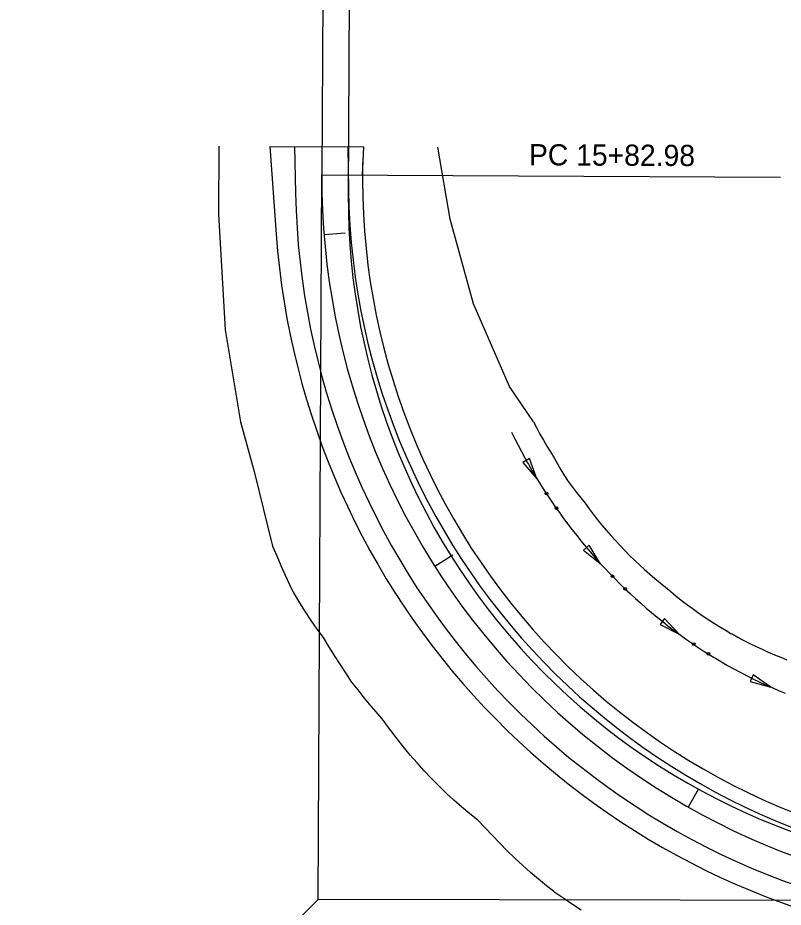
# Model space of a CAD drawing. Extents: x 1311167 to 1314552, y 2087587 to 2090602.
# Drawn here: x 1313606.1 to 1313823, y 2088407.4 to 2088659.3 of the extents above; entities that cross this region are included whole.
import ezdxf

# ---------------------------------------------------------------- set-up
doc = ezdxf.new("R2010")
doc.units = 0
for name, color, linetype in [('R_Horz Alg Stationing', 7, 'Continuous'), ('R_Proposed Road', 7, 'Continuous'), ('R_Shld_GR', 7, 'Continuous'), ('R_Shoulder', 7, 'Continuous'), ('S_DITCHLINE', 7, 'Continuous'), ('S_EDGE_CONCRETE', 7, 'Continuous'), ('S_EDGE_PAVEMENT', 7, 'Continuous'), ('S_PAVEMENT_CROWN', 7, 'Continuous')]:
    doc.layers.add(name, color=color, linetype=linetype)

msp = doc.modelspace()

# ---------------------------------------------------------------- linework, layer by layer
at = {"layer": 'R_Horz Alg Stationing'}
msp.add_line((1313700.19, 2088707.54), (1313699.7, 2088609.29), dxfattribs=at)
msp.add_arc((1313890.67, 2088608.34), 190.97, 179.7167, 269.7667, dxfattribs=at)
at = {"layer": 'R_Proposed Road'}
msp.add_line((1313692.64, 2088697.84), (1313692.23, 2088614.86), dxfattribs=at)
msp.add_line((1313692.64, 2088697.84), (1313692.23, 2088614.86), dxfattribs=at)
msp.add_arc((1313896.86, 2088613.85), 204.63, 179.7167, 269.8833, dxfattribs=at)
msp.add_arc((1313896.86, 2088613.85), 204.63, 179.7167, 269.8833, dxfattribs=at)
at = {"layer": 'R_Shld_GR'}
for points in [[(1313896.44, 2088409.22), (1313691.22, 2088409.64), (1313692.23, 2088614.86)], [(1313692.23, 2088614.86), (1313822.23, 2088614.22)], [(1313691.22, 2088409.64), (1313606.07, 2088325.08)]]:
    msp.add_lwpolyline(points, dxfattribs=at)
at = {"layer": 'R_Shoulder'}
for points in [[(1313698.84, 2088598.33), (1313692.86, 2088597.86)], [(1313729.3, 2088507.18), (1313724.24, 2088503.96)], [(1313799, 2088441), (1313796.04, 2088435.78)]]:
    msp.add_lwpolyline(points, dxfattribs=at)
at = {"layer": 'S_DITCHLINE'}
for p, q in [((1313751.04, 2088534.49), (1313749.22, 2088533.42)), ((1313749.22, 2088533.42), (1313753.15, 2088528.77)), ((1313753.15, 2088528.77), (1313751.04, 2088534.49)), ((1313767.98, 2088509.97), (1313766.38, 2088508.58)), ((1313771.13, 2088504.75), (1313767.98, 2088509.97)), ((1313766.38, 2088508.58), (1313771.13, 2088504.75)), ((1313789.32, 2088489.21), (1313788.05, 2088487.52)), ((1313788.05, 2088487.52), (1313793.47, 2088484.74)), ((1313793.47, 2088484.74), (1313789.32, 2088489.21)), ((1313814.45, 2088473.25), (1313813.55, 2088471.33)), ((1313819.44, 2088469.75), (1313814.45, 2088473.25)), ((1313813.55, 2088471.33), (1313819.44, 2088469.75))]:
    msp.add_line(p, q, dxfattribs=at)
for points in [[(1313745.99, 2088541.94), (1313746.89, 2088540.11), (1313747.82, 2088538.3), (1313748.77, 2088536.49), (1313749.74, 2088534.69), (1313750.53, 2088533.27), (1313750.74, 2088532.91), (1313751.77, 2088531.15), (1313752.81, 2088529.4), (1313753.88, 2088527.66), (1313754.98, 2088525.94), (1313756.09, 2088524.23), (1313757.22, 2088522.53), (1313758.37, 2088520.85), (1313759.55, 2088519.19), (1313760.74, 2088517.53), (1313761.95, 2088515.9), (1313763.18, 2088514.28), (1313764.44, 2088512.67), (1313765.71, 2088511.08), (1313767.01, 2088509.51), (1313768.33, 2088507.96), (1313769.66, 2088506.43), (1313771.02, 2088504.91), (1313772.4, 2088503.42), (1313773.8, 2088501.94), (1313775.22, 2088500.49), (1313776.65, 2088499.05), (1313778.11, 2088497.63), (1313779.58, 2088496.24), (1313781.08, 2088494.86), (1313782.59, 2088493.51), (1313784.12, 2088492.17), (1313785.66, 2088490.86), (1313787.23, 2088489.57), (1313788.81, 2088488.31), (1313790.4, 2088487.06), (1313792.02, 2088485.84), (1313793.64, 2088484.64), (1313795.29, 2088483.46), (1313796.95, 2088482.31), (1313798.62, 2088481.17), (1313800.31, 2088480.07), (1313802.01, 2088478.98), (1313803.41, 2088478.12), (1313803.73, 2088477.93), (1313805.47, 2088476.9), (1313807.22, 2088475.91), (1313808.98, 2088474.93), (1313810.75, 2088473.98), (1313812.54, 2088473.06), (1313814.34, 2088472.16), (1313816.14, 2088471.29), (1313817.96, 2088470.44), (1313819.79, 2088469.62), (1313821.63, 2088468.82), (1313823.47, 2088468.05)], [(1313745.99, 2088541.94), (1313746.89, 2088540.11), (1313747.82, 2088538.3), (1313748.77, 2088536.49), (1313749.74, 2088534.69), (1313750.53, 2088533.27), (1313750.74, 2088532.91), (1313751.77, 2088531.15), (1313752.81, 2088529.4), (1313753.19, 2088528.79)], [(1313761.6, 2088516.38), (1313761.62, 2088516.35)], [(1313761.62, 2088516.35), (1313761.95, 2088515.9), (1313763.18, 2088514.28), (1313764.44, 2088512.67), (1313765.71, 2088511.08), (1313767.01, 2088509.51), (1313768.33, 2088507.96), (1313769.66, 2088506.43), (1313771.02, 2088504.91), (1313771.15, 2088504.77)], [(1313781.8, 2088494.22), (1313781.83, 2088494.19)], [(1313781.83, 2088494.19), (1313782.59, 2088493.51), (1313784.12, 2088492.17), (1313785.66, 2088490.86), (1313787.23, 2088489.57), (1313788.81, 2088488.31), (1313790.4, 2088487.06), (1313792.02, 2088485.84), (1313793.48, 2088484.76)], [(1313806.04, 2088476.58), (1313806.08, 2088476.56)], [(1313806.08, 2088476.56), (1313807.22, 2088475.91), (1313808.98, 2088474.93), (1313810.75, 2088473.98), (1313812.54, 2088473.06), (1313814.34, 2088472.16), (1313816.14, 2088471.29), (1313817.96, 2088470.44), (1313819.45, 2088469.77)]]:
    msp.add_lwpolyline(points, dxfattribs=at)
for centre in [(1313755.9, 2088524.59), (1313758.71, 2088520.44), (1313774.61, 2088501.16), (1313778.17, 2088497.63), (1313797.6, 2088481.91), (1313801.79, 2088479.17)]:
    msp.add_circle(centre, 0.375, dxfattribs=at)
at = {"layer": 'S_EDGE_CONCRETE'}
for points in [[(1313663.07, 2088622.98), (1313662.92, 2088603.74), (1313664.81, 2088570.99), (1313669.2, 2088544.89), (1313673.04, 2088530.8), (1313678.23, 2088509.65)], [(1313752.19, 2088544.9), (1313745.4, 2088554.96), (1313735.17, 2088578.37), (1313728.59, 2088602.29), (1313725.13, 2088622.68)], [(1313752.19, 2088544.9), (1313753.1, 2088543.16), (1313754.03, 2088541.44), (1313754.99, 2088539.74), (1313755.98, 2088538.05), (1313756.79, 2088536.71), (1313757, 2088536.38), (1313758.02, 2088534.71), (1313758.98, 2088533.01), (1313759.97, 2088531.33), (1313760.98, 2088529.66), (1313762.05, 2088528.02), (1313763.21, 2088526.45), (1313764.39, 2088524.9), (1313765.6, 2088523.36), (1313766.82, 2088521.84), (1313767.98, 2088520.27), (1313769.15, 2088518.72), (1313770.35, 2088517.19), (1313771.57, 2088515.68), (1313772.82, 2088514.19), (1313774.1, 2088512.72), (1313775.41, 2088511.28), (1313776.74, 2088509.86), (1313778.08, 2088508.46), (1313779.45, 2088507.08), (1313780.83, 2088505.72), (1313782.24, 2088504.39), (1313783.67, 2088503.08), (1313785.12, 2088501.79), (1313786.59, 2088500.53), (1313788.09, 2088499.3), (1313789.6, 2088498.09), (1313791.07, 2088496.84), (1313792.56, 2088495.62), (1313794.07, 2088494.42), (1313795.59, 2088493.24), (1313797.14, 2088492.09), (1313798.7, 2088490.97), (1313800.28, 2088489.87), (1313801.89, 2088488.82), (1313803.52, 2088487.79), (1313805.15, 2088486.78), (1313806.79, 2088485.78), (1313808.15, 2088485), (1313808.45, 2088484.82), (1313810.13, 2088483.9), (1313811.83, 2088483), (1313813.54, 2088482.14), (1313815.26, 2088481.3), (1313816.99, 2088480.49), (1313818.73, 2088479.7), (1313820.48, 2088478.95), (1313822.24, 2088478.22), (1313824.01, 2088477.51)], [(1313678.23, 2088509.65), (1313679.5, 2088506.98), (1313680.63, 2088504.23), (1313681.83, 2088501.52), (1313683.08, 2088498.82), (1313684.12, 2088496.69), (1313684.42, 2088496.18), (1313685.93, 2088493.62), (1313687.5, 2088491.1), (1313689.13, 2088488.63), (1313690.82, 2088486.19), (1313692.56, 2088483.79)], [(1313692.56, 2088483.79), (1313694.16, 2088481.29), (1313695.71, 2088478.77), (1313697.29, 2088476.27), (1313698.89, 2088473.77), (1313700.53, 2088471.3), (1313702.38, 2088468.98), (1313704.25, 2088466.68), (1313706.14, 2088464.4), (1313708.05, 2088462.14), (1313709.97, 2088459.89)], [(1313765.73, 2088406.57), (1313763.23, 2088408.22), (1313760.76, 2088409.91), (1313758.29, 2088411.61), (1313757.84, 2088411.93), (1313755.93, 2088413.45), (1313753.61, 2088415.36), (1313751.34, 2088417.31), (1313749.1, 2088419.31), (1313746.91, 2088421.35), (1313744.75, 2088423.43), (1313742.64, 2088425.55), (1313740.57, 2088427.71), (1313738.54, 2088429.9), (1313736.47, 2088432.04), (1313734.16, 2088433.9), (1313731.89, 2088435.81), (1313729.66, 2088437.77), (1313727.48, 2088439.78), (1313725.34, 2088441.84), (1313723.25, 2088443.94), (1313721.21, 2088446.09), (1313719.21, 2088448.29), (1313717.27, 2088450.53), (1313715.37, 2088452.82), (1313713.53, 2088455.14), (1313711.74, 2088457.51), (1313709.97, 2088459.89)]]:
    msp.add_lwpolyline(points, dxfattribs=at)
at = {"layer": 'S_EDGE_PAVEMENT'}
for p, q in [((1313677.5, 2088622.91), (1313679.3, 2088598.06)), ((1313703.73, 2088614.81), (1313704.13, 2088622.78))]:
    msp.add_line(p, q, dxfattribs=at)
for radius, start, end in [(193.13, 178.6953, 269.8833), (218.13, 184.1502, 262.6016)]:
    msp.add_arc((1313896.86, 2088613.85), radius, start, end, dxfattribs=at)
at = {"layer": 'S_PAVEMENT_CROWN'}
for p, q in [((1313677.5, 2088622.91), (1313704.13, 2088622.78)), ((1313684.51, 2088622.88), (1313684.77, 2088609.64)), ((1313699.56, 2088622.8), (1313699.76, 2088610.64))]:
    msp.add_line(p, q, dxfattribs=at)
for radius, start, end in [(197.13, 180.9321, 269.8833), (212.13, 181.1378, 262.6016)]:
    msp.add_arc((1313896.86, 2088613.85), radius, start, end, dxfattribs=at)

# ---------------------------------------------------------------- texts
at = {"layer": 'R_Shld_GR'}
msp.add_text('PC 15+82.98', height=6, rotation=359.7167, dxfattribs=at).set_placement((1313750.9, 2088617.57))

doc.saveas('drawing.dxf')
